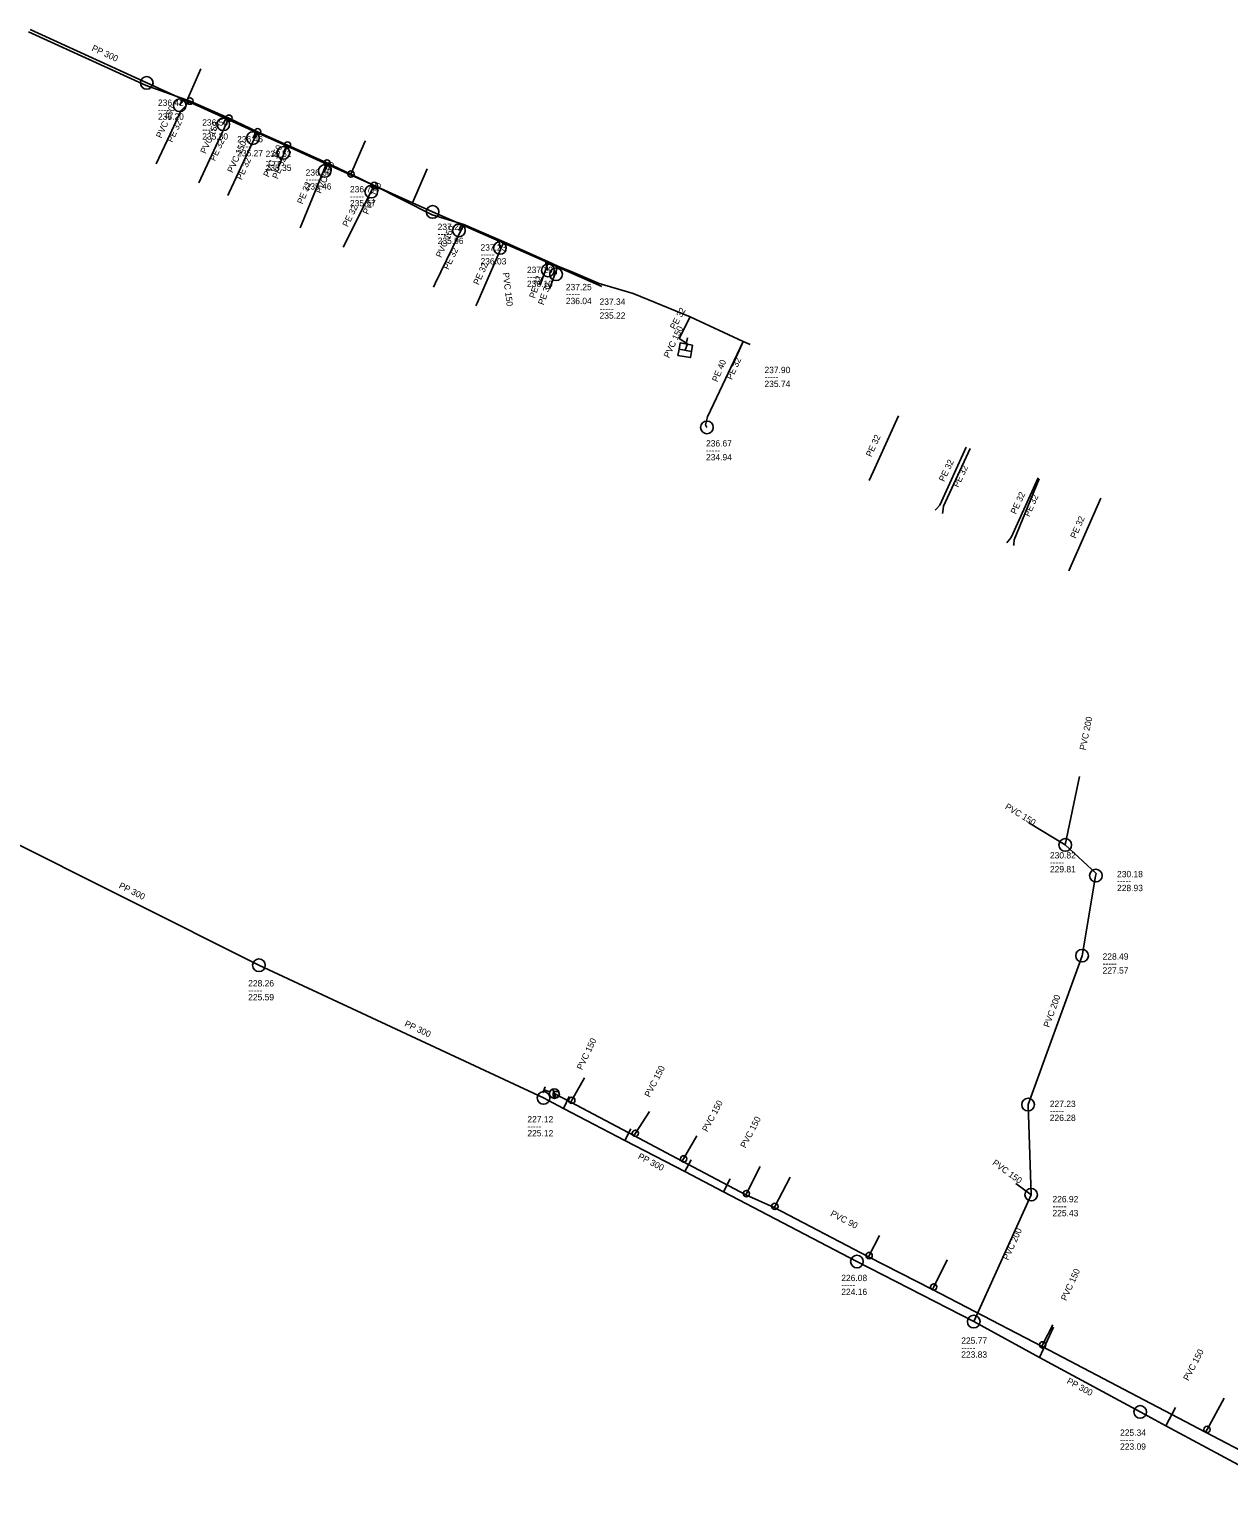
# Model space of a CAD drawing. Extents: x -771542 to -770341, y -1050442 to -1049881.
# Drawn here: x -771432.4 to -771242.8, y -1050118.2 to -1049885.3 of the extents above; entities that cross this region are included whole.
import ezdxf

# ---------------------------------------------------------------- set-up
doc = ezdxf.new("R2010")
doc.units = 0
doc.layers.add('Level 0', color=7, linetype='Continuous')

msp = doc.modelspace()

# ---------------------------------------------------------------- linework, layer by layer
at = {"layer": 'Level 0'}
for p, q in [((-771413.97, -1049894.18), (-771432.55, -1049885.68)), ((-771413.88, -1049893.75), (-771432.29, -1049885.31)), ((-771407.52, -1049896.62), (-771405.32, -1049891.52)), ((-771408.21, -1049896.31), (-771413.88, -1049893.75)), ((-771407.03, -1049896.64), (-771413.97, -1049894.18)), ((-771408.46, -1049898.18), (-771410.19, -1049901.89)), ((-771408.21, -1049896.31), (-771408.65, -1049897.29)), ((-771407.03, -1049896.64), (-771408.46, -1049898.18)), ((-771407.52, -1049896.62), (-771408.21, -1049896.31)), ((-771401.36, -1049899.4), (-771407.52, -1049896.62)), ((-771400.87, -1049899.34), (-771407.03, -1049896.64)), ((-771400.87, -1049899.34), (-771405.65, -1049909.56)), ((-771401.36, -1049899.4), (-771401.77, -1049900.31)), ((-771396.64, -1049901.53), (-771401.36, -1049899.4)), ((-771396.34, -1049901.49), (-771400.87, -1049899.34)), ((-771410.19, -1049901.89), (-771412.38, -1049906.58)), ((-771396.34, -1049901.49), (-771400.82, -1049911.07)), ((-771396.64, -1049901.53), (-771397.07, -1049902.48)), ((-771391.77, -1049903.73), (-771396.64, -1049901.53)), ((-771391.61, -1049903.59), (-771396.34, -1049901.49)), ((-771381.57, -1049908.17), (-771379.36, -1049903.1)), ((-771379.36, -1049903.1), (-771379.28, -1049902.92)), ((-771391.61, -1049903.59), (-771393.14, -1049907.29)), ((-771391.77, -1049903.73), (-771392.26, -1049904.82)), ((-771385.26, -1049906.67), (-771391.77, -1049903.73)), ((-771385.37, -1049906.42), (-771391.61, -1049903.59)), ((-771385.37, -1049906.42), (-771389.35, -1049916.05)), ((-771385.26, -1049906.67), (-771385.71, -1049907.67)), ((-771381.57, -1049908.17), (-771385.37, -1049906.42)), ((-771377.93, -1049909.98), (-771385.26, -1049906.67)), ((-771371.84, -1049912.73), (-771369.51, -1049907.37)), ((-771377.9, -1049909.97), (-771382.79, -1049919.72)), ((-771377.9, -1049909.97), (-771381.57, -1049908.17)), ((-771377.93, -1049909.98), (-771378.36, -1049910.95)), ((-771371.84, -1049912.73), (-771377.93, -1049909.98)), ((-771368.75, -1049914.61), (-771377.9, -1049909.97)), ((-771400.82, -1049911.07), (-771401.06, -1049911.59)), ((-771368.67, -1049914.16), (-771371.84, -1049912.73)), ((-771363.73, -1049916.15), (-771368.75, -1049914.61)), ((-771364.1, -1049916.17), (-771368.67, -1049914.16)), ((-771389.35, -1049916.05), (-771389.6, -1049916.65)), ((-771363.73, -1049916.15), (-771368.26, -1049925.5)), ((-771364.1, -1049916.17), (-771364.5, -1049917.08)), ((-771362, -1049917.09), (-771364.1, -1049916.17)), ((-771357.39, -1049918.91), (-771363.73, -1049916.15)), ((-771358.14, -1049918.79), (-771362, -1049917.09)), ((-771357.39, -1049918.91), (-771361.64, -1049928.57)), ((-771350.82, -1049922.01), (-771358.14, -1049918.79)), ((-771358.14, -1049918.79), (-771358.01, -1049919.85)), ((-771350.35, -1049922.04), (-771357.39, -1049918.91)), ((-771350.35, -1049922.04), (-771351.53, -1049925.42)), ((-771349.09, -1049922.77), (-771350.82, -1049922.01)), ((-771350.82, -1049922.01), (-771350.43, -1049923.4)), ((-771348.85, -1049922.75), (-771350.35, -1049922.04)), ((-771348.85, -1049922.75), (-771350.09, -1049926.07)), ((-771349.09, -1049922.77), (-771349.14, -1049924.02)), ((-771341.89, -1049925.94), (-771349.09, -1049922.77)), ((-771346.76, -1049923.59), (-771348.85, -1049922.75)), ((-771342.32, -1049925.5), (-771346.76, -1049923.59)), ((-771368.26, -1049925.5), (-771368.53, -1049926.06)), ((-771351.53, -1049925.42), (-771351.62, -1049925.69)), ((-771350.09, -1049926.07), (-771350.18, -1049926.32)), ((-771336.95, -1049927.06), (-771342.32, -1049925.5)), ((-771361.64, -1049928.57), (-771361.83, -1049928.99)), ((-771327.95, -1049930.73), (-771336.95, -1049927.06)), ((-771327.95, -1049930.73), (-771329.65, -1049934.19)), ((-771319.53, -1049934.65), (-771327.95, -1049930.73)), ((-771329.65, -1049934.19), (-771328.34, -1049935.02)), ((-771328.34, -1049935.02), (-771328.71, -1049936.04)), ((-771328.36, -1049934.07), (-771328.54, -1049935.06)), ((-771319.53, -1049934.65), (-771325.18, -1049946.58)), ((-771319.53, -1049934.65), (-771321.3, -1049938.55)), ((-771318.46, -1049935.12), (-771319.53, -1049934.65)), ((-771325.18, -1049946.58), (-771325.48, -1049947.83)), ((-771294.96, -1049946.41), (-771298.98, -1049955.26)), ((-771325.48, -1049947.83), (-771325.28, -1049948.24)), ((-771284.27, -1049951.34), (-771288.43, -1049960.51)), ((-771283.63, -1049951.55), (-771287.89, -1049960.69)), ((-771298.98, -1049955.26), (-771299.6, -1049956.63)), ((-771272.91, -1049956.18), (-771277.15, -1049965.62)), ((-771272.72, -1049956.36), (-771276.7, -1049966)), ((-771289.01, -1049961.14), (-771289.18, -1049961.33)), ((-771288.43, -1049960.51), (-771289.01, -1049961.14)), ((-771287.89, -1049960.69), (-771287.98, -1049961.59)), ((-771262.96, -1049959.41), (-771268.02, -1049970.92)), ((-771287.98, -1049961.59), (-771288.01, -1049961.86)), ((-771277.15, -1049965.62), (-771277.69, -1049966.28)), ((-771276.7, -1049966), (-771276.76, -1049966.75)), ((-771277.69, -1049966.28), (-771277.83, -1049966.46)), ((-771276.76, -1049966.75), (-771276.78, -1049966.93)), ((-771268.61, -1050014.25), (-771266.36, -1050003.42)), ((-771441.51, -1050010.52), (-771396.12, -1050033.28)), ((-771268.61, -1050014.25), (-771274.36, -1050010.77)), ((-771268.61, -1050014.25), (-771263.74, -1050018.75)), ((-771263.81, -1050019.17), (-771265.95, -1050031.76)), ((-771263.74, -1050018.75), (-771263.81, -1050019.17)), ((-771396.12, -1050033.28), (-771351.12, -1050054.26)), ((-771265.95, -1050031.76), (-771274.49, -1050055.3)), ((-771346.65, -1050054.63), (-771344.63, -1050051.07)), ((-771351.23, -1050053.44), (-771350.88, -1050052.5)), ((-771351.12, -1050054.26), (-771347.95, -1050055.91)), ((-771350.11, -1050053.31), (-771351.05, -1050052.97)), ((-771349.18, -1050054.28), (-771349.64, -1050052.86)), ((-771349.12, -1050053.72), (-771349.41, -1050053.57)), ((-771346.82, -1050054.93), (-771349.12, -1050053.72)), ((-771347.95, -1050055.91), (-771347.05, -1050054.03)), ((-771347.95, -1050055.91), (-771338.24, -1050060.98)), ((-771346.82, -1050054.93), (-771346.65, -1050054.63)), ((-771336.83, -1050060.21), (-771346.82, -1050054.93)), ((-771336.59, -1050059.84), (-771334.38, -1050056.42)), ((-771274.49, -1050055.3), (-771274, -1050069.55)), ((-771338.24, -1050060.98), (-771337.29, -1050059.14)), ((-771338.24, -1050060.98), (-771328.78, -1050065.91)), ((-771336.83, -1050060.21), (-771336.59, -1050059.84)), ((-771329.18, -1050064.25), (-771336.83, -1050060.21)), ((-771328.97, -1050063.89), (-771326.85, -1050060.27)), ((-771329.18, -1050064.25), (-771328.97, -1050063.89)), ((-771319.13, -1050069.56), (-771329.18, -1050064.25)), ((-771328.78, -1050065.91), (-771327.79, -1050064.03)), ((-771328.78, -1050065.91), (-771322.66, -1050069.11)), ((-771319.04, -1050069.38), (-771316.86, -1050065.09)), ((-771322.66, -1050069.11), (-771321.58, -1050067.03)), ((-771314.53, -1050071.4), (-771312.13, -1050066.76)), ((-771274, -1050069.55), (-771276.45, -1050067.77)), ((-771322.66, -1050069.11), (-771301.56, -1050080.12)), ((-771319.13, -1050069.56), (-771319.04, -1050069.38)), ((-771314.63, -1050071.59), (-771319.13, -1050069.56)), ((-771274, -1050069.55), (-771283.09, -1050089.62)), ((-771314.63, -1050071.59), (-771314.53, -1050071.4)), ((-771299.71, -1050079.36), (-771314.63, -1050071.59)), ((-771299.62, -1050079.18), (-771297.98, -1050075.99)), ((-771301.56, -1050080.12), (-771283.09, -1050089.62)), ((-771299.71, -1050079.36), (-771299.62, -1050079.18)), ((-771289.62, -1050084.56), (-771299.71, -1050079.36)), ((-771289.41, -1050084.14), (-771287.27, -1050079.84)), ((-771289.62, -1050084.56), (-771289.41, -1050084.14)), ((-771272.24, -1050093.56), (-771289.62, -1050084.56)), ((-771283.09, -1050089.62), (-771272.66, -1050095.28)), ((-771272.66, -1050095.28), (-771270.48, -1050090.49)), ((-771272.19, -1050093.3), (-771270.56, -1050090.11)), ((-771272.24, -1050093.56), (-771272.19, -1050093.3)), ((-771246.42, -1050107.1), (-771272.24, -1050093.56)), ((-771272.66, -1050095.28), (-771256.76, -1050103.91)), ((-771252.68, -1050106.1), (-771251.18, -1050103.21)), ((-771246.19, -1050106.68), (-771243.49, -1050101.74)), ((-771256.76, -1050103.91), (-771252.68, -1050106.1)), ((-771252.68, -1050106.1), (-771230.08, -1050118.23)), ((-771246.42, -1050107.1), (-771246.19, -1050106.68)), ((-771238.56, -1050111.22), (-771246.42, -1050107.1))]:
    msp.add_line(p, q, dxfattribs=at)
msp.add_lwpolyline([(-771327.55, -1049935.23), (-771329.52, -1049934.88), (-771329.69, -1049935.87), (-771327.73, -1049936.21)], close=True, dxfattribs=at)
msp.add_lwpolyline([(-771327.73, -1049936.21), (-771327.9, -1049937.2), (-771329.87, -1049936.85), (-771329.69, -1049935.87)], dxfattribs=at)
for centre, radius in [((-771413.88, -1049893.75), 1), ((-771407.03, -1049896.64), 0.5), ((-771408.65, -1049897.29), 1), ((-771401.77, -1049900.31), 1), ((-771400.87, -1049899.34), 0.5), ((-771397.07, -1049902.48), 1), ((-771396.34, -1049901.49), 0.5), ((-771391.61, -1049903.59), 0.5), ((-771392.26, -1049904.82), 1), ((-771385.71, -1049907.67), 1), ((-771385.37, -1049906.42), 0.5), ((-771381.57, -1049908.17), 0.5), ((-771378.36, -1049910.95), 1), ((-771377.9, -1049909.97), 0.5), ((-771368.67, -1049914.16), 1), ((-771364.5, -1049917.08), 1), ((-771358.01, -1049919.85), 1), ((-771350.43, -1049923.4), 1), ((-771349.14, -1049924.02), 1), ((-771325.28, -1049948.24), 1), ((-771268.61, -1050014.25), 1), ((-771263.77, -1050019.09), 1), ((-771265.95, -1050031.76), 1), ((-771396.12, -1050033.28), 1), ((-771351.12, -1050054.26), 1), ((-771349.41, -1050053.57), 0.75), ((-771349.12, -1050053.72), 0.5), ((-771346.65, -1050054.63), 0.5), ((-771274.49, -1050055.3), 1), ((-771336.59, -1050059.84), 0.5), ((-771328.97, -1050063.89), 0.5), ((-771274, -1050069.55), 1), ((-771319.04, -1050069.38), 0.5), ((-771314.53, -1050071.4), 0.5), ((-771301.56, -1050080.12), 1), ((-771299.62, -1050079.18), 0.5), ((-771289.41, -1050084.14), 0.5), ((-771283.09, -1050089.62), 1), ((-771272.19, -1050093.3), 0.5), ((-771256.76, -1050103.91), 1), ((-771246.19, -1050106.68), 0.5)]:
    msp.add_circle(centre, radius, dxfattribs=at)

# ---------------------------------------------------------------- texts
for s, rotation, p in [('PP 300', 335.371, (-771422.67, -1049888.62)), ('PVC 150', 65.821, (-771411.55, -1049902.59)), ('PE 32', 65, (-771409.82, -1049903.25)), ('PVC 150', 65.746, (-771404.54, -1049905.05)), ('PE 32', 64.934, (-771403.08, -1049906.2)), ('PVC 150', 65.647, (-771400.29, -1049908.06)), ('PVC 150', 65.794, (-771394.59, -1049908.74)), ('PE 32', 67.534, (-771393.16, -1049909.03)), ('PE 32', 65.225, (-771398.86, -1049909.19)), ('PVC 150', 65.772, (-771386.33, -1049911.34)), ('PE 32', 67.38, (-771389.22, -1049913.02)), ('PVC 150', 66.092, (-771378.86, -1049914.65)), ('PE 32', 63.364, (-771382.09, -1049916.62)), ('PVC 150', 66.272, (-771367.3, -1049921.47)), ('PE 32', 64.259, (-771366.15, -1049923.38)), ('PE 32', 65.659, (-771361.38, -1049925.79)), ('PVC 150', 276.992, (-771357.58, -1049923.8)), ('PE 32', 71.565, (-771352.48, -1049927.9)), ('PE 32', 70.201, (-771351.1, -1049928.96)), ('PE 32', 61.476, (-771330.33, -1049932.84)), ('PVC 150', 64.739, (-771331.28, -1049937.34)), ('PE 40', 67.162, (-771323.61, -1049941.13)), ('PE 32', 65.589, (-771321.33, -1049940.78)), ('PE 32', 65.651, (-771299.28, -1049952.98)), ('PE 32', 64.485, (-771287.76, -1049956.9)), ('PE 32', 64.522, (-771285.52, -1049957.81)), ('PE 32', 65.721, (-771276.4, -1049962.04)), ('PE 32', 66.395, (-771274.28, -1049962.44)), ('PE 32', 66.269, (-771266.96, -1049965.88)), ('PVC 200', 78.263, (-771265.4, -1049999.33)), ('PVC 150', 328.817, (-771278.23, -1050008.47)), ('PP 300', 333.369, (-771418.37, -1050021.01)), ('PVC 200', 70.06, (-771271.16, -1050043.19)), ('PP 300', 335.004, (-771373.2, -1050042.86)), ('PVC 150', 64.418, (-771345.02, -1050049.92)), ('PVC 150', 62.692, (-771334.33, -1050054.23)), ('PVC 150', 62.229, (-771325.22, -1050059.7)), ('PVC 150', 62.56, (-771319.17, -1050062.27)), ('PP 300', 332.474, (-771336.28, -1050063.81)), ('PVC 150', 324, (-771280.23, -1050064.73)), ('PVC 90', 332.491, (-771305.84, -1050072.85)), ('PVC 200', 65.634, (-771277.63, -1050080)), ('PVC 150', 65.529, (-771268.45, -1050086.41)), ('PVC 150', 62.569, (-771249.13, -1050099.06)), ('PP 300', 331.508, (-771268.46, -1050099.33))]:
    msp.add_text(s, height=1, rotation=rotation, dxfattribs=at).set_placement(p)
for s, p in [('-----', (-771412.09, -1049898.49)), ('236.42', (-771412.09, -1049897.39)), ('235.20', (-771412.09, -1049899.59)), ('236.50', (-771405.1, -1049900.52)), ('-----', (-771405.1, -1049901.62)), ('235.30', (-771405.1, -1049902.72)), ('236.46', (-771399.58, -1049903.17)), ('-----', (-771399.58, -1049904.27)), ('235.27', (-771399.58, -1049905.37)), ('236.52', (-771395.07, -1049905.48)), ('-----', (-771395.07, -1049906.58)), ('235.35', (-771395.07, -1049907.68)), ('236.66', (-771388.74, -1049908.42)), ('-----', (-771388.74, -1049909.52)), ('235.46', (-771388.74, -1049910.62)), ('236.77', (-771381.73, -1049911.07)), ('-----', (-771381.73, -1049912.17)), ('235.57', (-771381.73, -1049913.27)), ('237.23', (-771367.86, -1049917.02)), ('-----', (-771367.86, -1049918.12)), ('235.96', (-771367.86, -1049919.22)), ('237.23', (-771361.09, -1049920.27)), ('-----', (-771361.09, -1049921.37)), ('236.03', (-771361.09, -1049922.47)), ('237.29', (-771353.74, -1049923.83)), ('-----', (-771353.74, -1049924.93)), ('236.10', (-771353.74, -1049926.03)), ('237.25', (-771347.59, -1049926.54)), ('-----', (-771347.59, -1049927.64)), ('236.04', (-771347.59, -1049928.74)), ('237.34', (-771342.26, -1049928.85)), ('-----', (-771342.26, -1049929.95)), ('235.22', (-771342.26, -1049931.05)), ('-----', (-771316.18, -1049940.75)), ('237.90', (-771316.18, -1049939.65)), ('235.74', (-771316.18, -1049941.85)), ('-----', (-771325.42, -1049952.35)), ('236.67', (-771325.42, -1049951.25)), ('234.94', (-771325.42, -1049953.45)), ('-----', (-771271.03, -1050017.49)), ('230.82', (-771271.03, -1050016.39)), ('229.81', (-771271.03, -1050018.59)), ('230.18', (-771260.42, -1050019.36)), ('-----', (-771260.42, -1050020.46)), ('228.93', (-771260.42, -1050021.56)), ('-----', (-771262.7, -1050033.49)), ('228.49', (-771262.7, -1050032.39)), ('227.57', (-771262.7, -1050034.59)), ('228.26', (-771397.83, -1050036.63)), ('-----', (-771397.83, -1050037.73)), ('225.59', (-771397.83, -1050038.83)), ('-----', (-771271.05, -1050056.79)), ('227.23', (-771271.05, -1050055.69)), ('226.28', (-771271.05, -1050057.89)), ('-----', (-771353.67, -1050059.23)), ('227.12', (-771353.67, -1050058.13)), ('225.12', (-771353.67, -1050060.33)), ('226.92', (-771270.63, -1050070.76)), ('-----', (-771270.63, -1050071.86)), ('225.43', (-771270.63, -1050072.96)), ('226.08', (-771304.03, -1050083.22)), ('-----', (-771304.03, -1050084.32)), ('224.16', (-771304.03, -1050085.42)), ('-----', (-771285.06, -1050094.23)), ('225.77', (-771285.06, -1050093.13)), ('223.83', (-771285.06, -1050095.33)), ('225.34', (-771259.94, -1050107.68)), ('-----', (-771259.94, -1050108.78)), ('223.09', (-771259.94, -1050109.88))]:
    msp.add_text(s, height=1, dxfattribs=at).set_placement(p)

doc.saveas('drawing.dxf')
